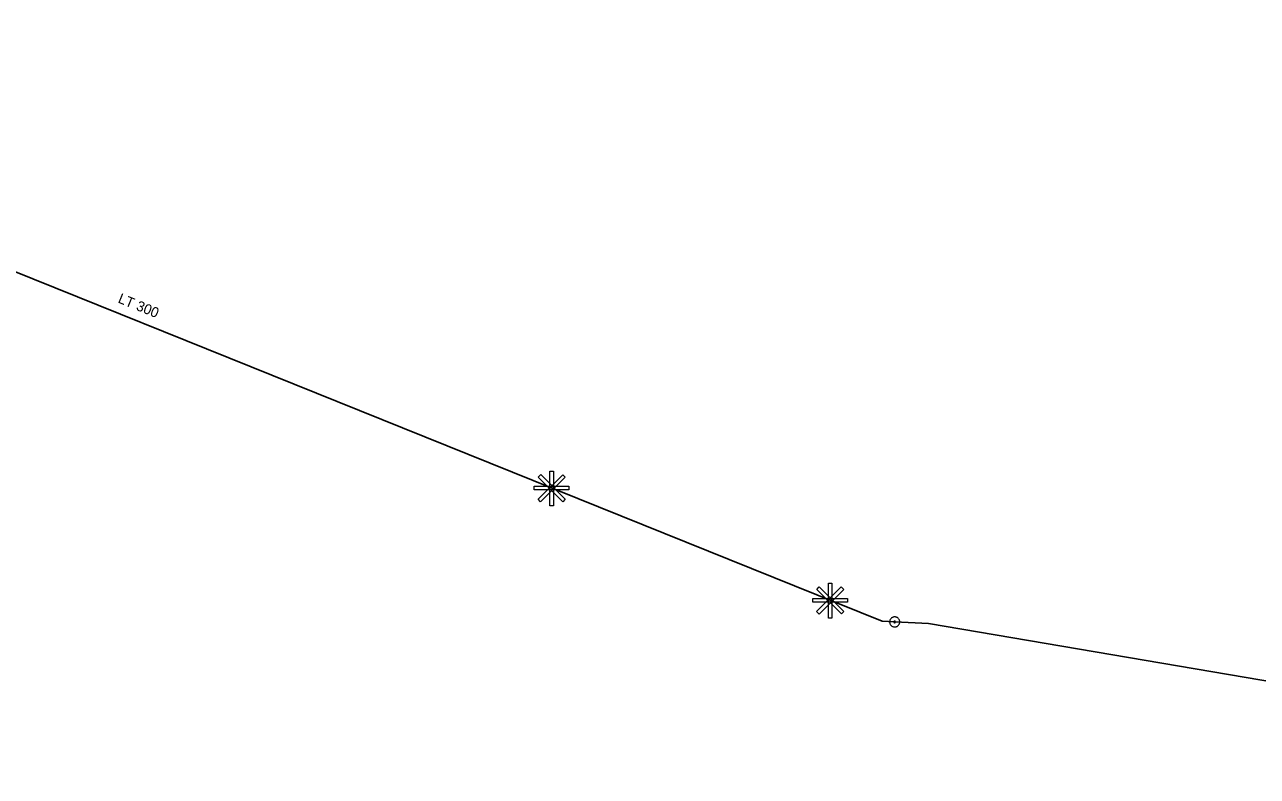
# Model space of a CAD drawing. Extents: x -809028 to -807737, y -990545 to -989489.
# Drawn here: x -808548.3 to -808426.5, y -989760.9 to -989686.7 of the extents above; entities that cross this region are included whole.
import ezdxf

# ---------------------------------------------------------------- set-up
doc = ezdxf.new("R2010")
doc.units = 0
doc.header["$LTSCALE"] = 0.32
for name, color, linetype, lineweight in [('1', 7, 'Continuous', 13), ('12', 7, 'Continuous', 13), ('17', 7, 'Continuous', 25), ('47', 7, 'Continuous', 13)]:
    doc.layers.add(name, color=color, linetype=linetype, lineweight=lineweight)

msp = doc.modelspace()

# ---------------------------------------------------------------- linework, layer by layer
at = {"layer": '12'}
for points in [[(-808495.145, -989731.118), (-808494.897, -989731.366), (-808497.326, -989733.795), (-808497.573, -989733.547)], [(-808497.564, -989731.357), (-808497.317, -989731.109), (-808494.888, -989733.538), (-808495.135, -989733.786)], [(-808496.411, -989730.754), (-808496.061, -989730.754), (-808496.061, -989734.189), (-808496.411, -989734.189)], [(-808494.527, -989732.263), (-808494.527, -989732.613), (-808497.962, -989732.613), (-808497.962, -989732.263)], [(-808467.637, -989742.199), (-808467.389, -989742.447), (-808469.818, -989744.876), (-808470.065, -989744.628)], [(-808470.056, -989742.438), (-808469.809, -989742.19), (-808467.38, -989744.619), (-808467.627, -989744.867)], [(-808468.903, -989741.835), (-808468.553, -989741.835), (-808468.553, -989745.27), (-808468.903, -989745.27)], [(-808467.019, -989743.344), (-808467.019, -989743.694), (-808470.454, -989743.694), (-808470.454, -989743.344)]]:
    msp.add_lwpolyline(points, close=True, dxfattribs=at)
at = {"layer": '17'}
for points in [[(-808462.359, -989745.649), (-808463.609, -989745.59), (-808609.824, -989686.686), (-808669.927, -989715.25), (-808715.085, -989727.543), (-808715.98, -989727.807)], [(-808290.19, -989739.32), (-808293.653, -989740.254), (-808370.142, -989760.894), (-808459.01, -989745.809), (-808462.359, -989745.649)]]:
    msp.add_lwpolyline(points, dxfattribs=at)
at = {"layer": '47'}
for points in [[(-808462.858, -989745.625), (-808462.857, -989745.677), (-808462.852, -989745.729), (-808462.84, -989745.78), (-808462.825, -989745.829), (-808462.803, -989745.878), (-808462.776, -989745.923), (-808462.745, -989745.964), (-808462.71, -989746.003), (-808462.671, -989746.038), (-808462.629, -989746.069), (-808462.583, -989746.095), (-808462.535, -989746.116), (-808462.486, -989746.132), (-808462.434, -989746.142), (-808462.382, -989746.148), (-808462.33, -989746.147), (-808462.278, -989746.142), (-808462.226, -989746.13), (-808462.178, -989746.115), (-808462.129, -989746.093), (-808462.084, -989746.066), (-808462.042, -989746.035), (-808462.003, -989746), (-808461.968, -989745.962), (-808461.938, -989745.919), (-808461.912, -989745.873), (-808461.89, -989745.825), (-808461.875, -989745.776), (-808461.865, -989745.724), (-808461.859, -989745.672), (-808461.86, -989745.62), (-808461.865, -989745.568), (-808461.876, -989745.516), (-808461.892, -989745.468), (-808461.914, -989745.419), (-808461.94, -989745.374), (-808461.971, -989745.332), (-808462.006, -989745.293), (-808462.045, -989745.258), (-808462.088, -989745.228), (-808462.134, -989745.202), (-808462.181, -989745.18), (-808462.231, -989745.165), (-808462.283, -989745.155), (-808462.335, -989745.149), (-808462.387, -989745.15), (-808462.439, -989745.155), (-808462.49, -989745.166), (-808462.539, -989745.182), (-808462.588, -989745.204), (-808462.633, -989745.23), (-808462.674, -989745.261), (-808462.713, -989745.296), (-808462.748, -989745.336), (-808462.779, -989745.378), (-808462.805, -989745.424), (-808462.826, -989745.471), (-808462.842, -989745.521), (-808462.852, -989745.573)], [(-808462.44, -989745.645), (-808462.441, -989745.654), (-808462.439, -989745.662), (-808462.438, -989745.67), (-808462.435, -989745.678), (-808462.431, -989745.686), (-808462.427, -989745.693), (-808462.422, -989745.701), (-808462.416, -989745.707), (-808462.41, -989745.712), (-808462.403, -989745.717), (-808462.395, -989745.722), (-808462.387, -989745.725), (-808462.379, -989745.728), (-808462.371, -989745.73), (-808462.362, -989745.73), (-808462.353, -989745.731), (-808462.345, -989745.729), (-808462.337, -989745.728), (-808462.329, -989745.725), (-808462.321, -989745.721), (-808462.314, -989745.717), (-808462.306, -989745.712), (-808462.3, -989745.706), (-808462.294, -989745.7), (-808462.29, -989745.693), (-808462.285, -989745.685), (-808462.282, -989745.677), (-808462.279, -989745.669), (-808462.277, -989745.661), (-808462.277, -989745.652), (-808462.276, -989745.643), (-808462.278, -989745.635), (-808462.279, -989745.627), (-808462.282, -989745.619), (-808462.286, -989745.611), (-808462.289, -989745.604), (-808462.295, -989745.596), (-808462.301, -989745.59), (-808462.307, -989745.584), (-808462.314, -989745.58), (-808462.322, -989745.575), (-808462.33, -989745.572), (-808462.338, -989745.569), (-808462.346, -989745.567), (-808462.355, -989745.567), (-808462.364, -989745.566), (-808462.372, -989745.568), (-808462.38, -989745.569), (-808462.388, -989745.572), (-808462.396, -989745.576), (-808462.403, -989745.579), (-808462.411, -989745.585), (-808462.417, -989745.591), (-808462.422, -989745.597), (-808462.427, -989745.604), (-808462.432, -989745.612), (-808462.435, -989745.62), (-808462.438, -989745.628), (-808462.44, -989745.636)]]:
    msp.add_lwpolyline(points, close=True, dxfattribs=at)

# ---------------------------------------------------------------- texts
at = {"layer": '1'}
msp.add_text('LT 300', height=1, rotation=338, dxfattribs=at).set_placement((-808539.13, -989714.102))

doc.saveas('drawing.dxf')
